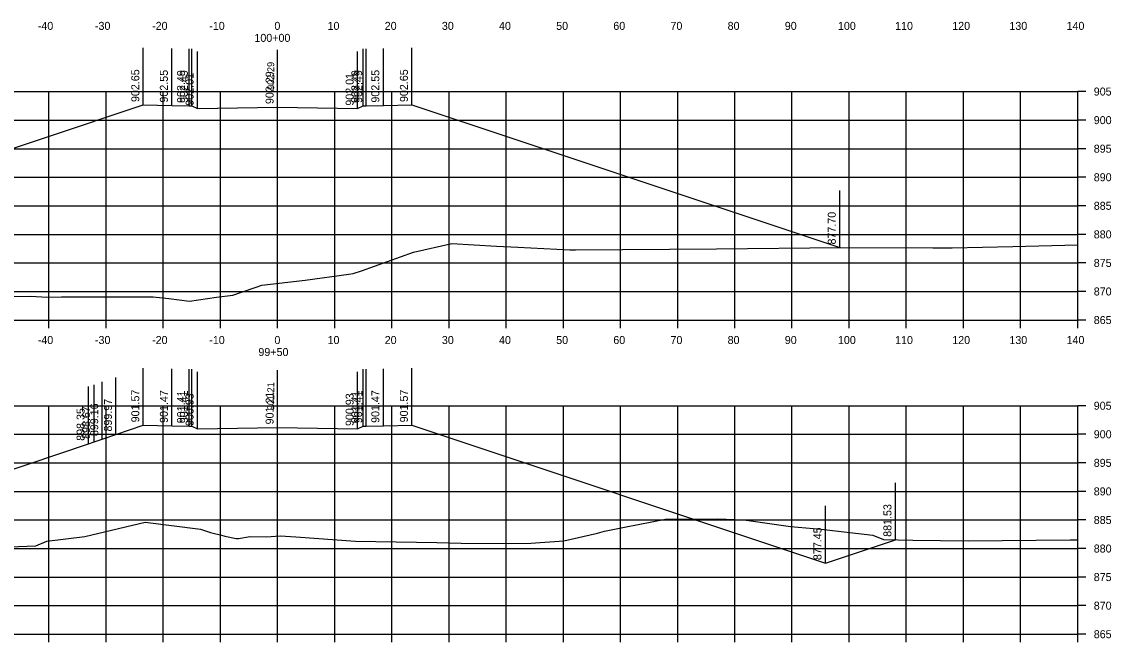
# Model space of a CAD drawing. Extents: x 1098669 to 1198896, y 698679 to 704410.
# Drawn here: x 1111950.8 to 1112141.4, y 701694.6 to 701803.2 of the extents above; entities that cross this region are included whole.
import ezdxf

# ---------------------------------------------------------------- set-up
doc = ezdxf.new("R2010")
doc.units = 0
for name, color, linetype in [('59', 7, 'Continuous'), ('Proposed Surface', 7, 'Continuous'), ('R_Axis', 7, 'Continuous'), ('R_Axis Annot', 7, 'Continuous'), ('R_Fin Surface', 7, 'Continuous'), ('R_Grid', 7, 'Continuous'), ('R_Xsect Elev', 7, 'Continuous')]:
    doc.layers.add(name, color=color, linetype=linetype)

msp = doc.modelspace()

# ---------------------------------------------------------------- linework, layer by layer
at = {"layer": 'Proposed Surface'}
for points in [[(1111945.38, 701755.1), (1111952.3, 701755.23), (1111954.32, 701755.09), (1111955.13, 701755.02), (1111957.71, 701755.07), (1111963.16, 701755.11), (1111971.64, 701755.12), (1111973.75, 701755.12), (1111976.54, 701754.78), (1111980.14, 701754.33), (1111984.83, 701755.05), (1111987.72, 701755.36), (1111989.24, 701755.9), (1111991.82, 701756.8), (1111992.79, 701757.15), (1112000.38, 701757.99), (1112008, 701759.06), (1112008.77, 701759.17), (1112010.21, 701759.64), (1112019.3, 701762.94), (1112026.03, 701764.45), (1112033.84, 701763.99), (1112037.6, 701763.8), (1112046.66, 701763.34), (1112047.11, 701763.32), (1112047.14, 701763.31), (1112047.26, 701763.31), (1112047.66, 701763.31), (1112072.33, 701763.49), (1112094.11, 701763.73), (1112110.22, 701763.69), (1112113.57, 701763.67), (1112124.19, 701763.92), (1112135.55, 701764.22)], [(1111948.71, 701711.3), (1111953.23, 701711.49), (1111955.19, 701712.33), (1111961.8, 701713.15), (1111972.36, 701715.67), (1111982.04, 701714.42), (1111983.8, 701713.85), (1111984.73, 701713.58), (1111985.57, 701713.42), (1111986.32, 701713.18), (1111988.28, 701712.78), (1111988.71, 701712.79), (1111990.74, 701713.13), (1111993.62, 701713.09), (1111995.97, 701713.23), (1111998.76, 701713.09), (1112009.18, 701712.33), (1112023.41, 701712.1), (1112027.65, 701711.95), (1112035.91, 701711.93), (1112039.87, 701711.99), (1112045.66, 701712.35), (1112051.52, 701713.71), (1112052.72, 701714.06), (1112056.27, 701714.77), (1112063.43, 701716.15), (1112066.88, 701716.17), (1112072.51, 701716.24), (1112077.13, 701716.06), (1112085.28, 701714.91), (1112090.68, 701714.44), (1112099.67, 701713.36), (1112101.58, 701712.6), (1112106.69, 701712.49), (1112116.36, 701712.35), (1112134.24, 701712.53), (1112135.55, 701712.57)]]:
    msp.add_lwpolyline(points, dxfattribs=at)
at = {"layer": 'R_Axis'}
for p, q in [((1112135.55, 701751.03), (1112135.55, 701791.03)), ((1112136.95, 701791.03), (1112135.55, 701791.03)), ((1112136.95, 701786.03), (1112135.55, 701786.03)), ((1112136.95, 701781.03), (1112135.55, 701781.03)), ((1112136.95, 701776.03), (1112135.55, 701776.03)), ((1112136.95, 701771.03), (1112135.55, 701771.03)), ((1112136.95, 701766.03), (1112135.55, 701766.03)), ((1112136.95, 701761.03), (1112135.55, 701761.03)), ((1112136.95, 701756.03), (1112135.55, 701756.03)), ((1111855.55, 701751.03), (1112135.55, 701751.03)), ((1111955.55, 701749.63), (1111955.55, 701751.03)), ((1111965.55, 701749.63), (1111965.55, 701751.03)), ((1111975.55, 701749.63), (1111975.55, 701751.03)), ((1111985.55, 701749.63), (1111985.55, 701751.03)), ((1111995.55, 701749.63), (1111995.55, 701751.03)), ((1112005.55, 701749.63), (1112005.55, 701751.03)), ((1112015.55, 701749.63), (1112015.55, 701751.03)), ((1112025.55, 701749.63), (1112025.55, 701751.03)), ((1112035.55, 701749.63), (1112035.55, 701751.03)), ((1112045.55, 701749.63), (1112045.55, 701751.03)), ((1112055.55, 701749.63), (1112055.55, 701751.03)), ((1112065.55, 701749.63), (1112065.55, 701751.03)), ((1112075.55, 701749.63), (1112075.55, 701751.03)), ((1112085.55, 701749.63), (1112085.55, 701751.03)), ((1112095.55, 701749.63), (1112095.55, 701751.03)), ((1112105.55, 701749.63), (1112105.55, 701751.03)), ((1112115.55, 701749.63), (1112115.55, 701751.03)), ((1112125.55, 701749.63), (1112125.55, 701751.03)), ((1112135.55, 701749.63), (1112135.55, 701751.03)), ((1112136.95, 701751.03), (1112135.55, 701751.03)), ((1112135.55, 701696.03), (1112135.55, 701736.03)), ((1112136.95, 701736.03), (1112135.55, 701736.03)), ((1112136.95, 701731.03), (1112135.55, 701731.03)), ((1112136.95, 701726.03), (1112135.55, 701726.03)), ((1112136.95, 701721.03), (1112135.55, 701721.03)), ((1112136.95, 701716.03), (1112135.55, 701716.03)), ((1112136.95, 701711.03), (1112135.55, 701711.03)), ((1112136.95, 701706.03), (1112135.55, 701706.03)), ((1112136.95, 701701.03), (1112135.55, 701701.03)), ((1111855.55, 701696.03), (1112135.55, 701696.03)), ((1111955.55, 701694.63), (1111955.55, 701696.03)), ((1111965.55, 701694.63), (1111965.55, 701696.03)), ((1111975.55, 701694.63), (1111975.55, 701696.03)), ((1111985.55, 701694.63), (1111985.55, 701696.03)), ((1111995.55, 701694.63), (1111995.55, 701696.03)), ((1112005.55, 701694.63), (1112005.55, 701696.03)), ((1112015.55, 701694.63), (1112015.55, 701696.03)), ((1112025.55, 701694.63), (1112025.55, 701696.03)), ((1112035.55, 701694.63), (1112035.55, 701696.03)), ((1112045.55, 701694.63), (1112045.55, 701696.03)), ((1112055.55, 701694.63), (1112055.55, 701696.03)), ((1112065.55, 701694.63), (1112065.55, 701696.03)), ((1112075.55, 701694.63), (1112075.55, 701696.03)), ((1112085.55, 701694.63), (1112085.55, 701696.03)), ((1112095.55, 701694.63), (1112095.55, 701696.03)), ((1112105.55, 701694.63), (1112105.55, 701696.03)), ((1112115.55, 701694.63), (1112115.55, 701696.03)), ((1112125.55, 701694.63), (1112125.55, 701696.03)), ((1112135.55, 701694.63), (1112135.55, 701696.03)), ((1112136.95, 701696.03), (1112135.55, 701696.03))]:
    msp.add_line(p, q, dxfattribs=at)
at = {"layer": 'R_Fin Surface'}
for points in [[(1111900.33, 701764.77), (1111920.41, 701771.45), (1111926.15, 701773.37), (1111937.63, 701777.2), (1111972.05, 701788.68), (1111977.05, 701788.58), (1111980.05, 701788.52), (1111980.55, 701788.52), (1111981.55, 701788.04), (1111995.55, 701788.32), (1112009.55, 701788.04), (1112010.55, 701788.52), (1112011.05, 701788.52), (1112014.05, 701788.58), (1112019.05, 701788.68), (1112093.91, 701763.73)], [(1111946.63, 701724.06), (1111962.48, 701729.37), (1111963.44, 701729.7), (1111964.87, 701730.19), (1111967.27, 701730.99), (1111972.05, 701732.6), (1111977.05, 701732.5), (1111980.05, 701732.44), (1111980.55, 701732.44), (1111981.55, 701731.96), (1111995.55, 701732.24), (1112009.55, 701731.96), (1112010.55, 701732.44), (1112011.05, 701732.44), (1112014.05, 701732.5), (1112019.05, 701732.6), (1112091.41, 701708.48), (1112103.65, 701712.56)]]:
    msp.add_lwpolyline(points, dxfattribs=at)
at = {"layer": 'R_Grid'}
for p, q in [((1111855.55, 701791.03), (1112135.55, 701791.03)), ((1111955.55, 701751.03), (1111955.55, 701791.03)), ((1111965.55, 701751.03), (1111965.55, 701791.03)), ((1111975.55, 701751.03), (1111975.55, 701791.03)), ((1111985.55, 701751.03), (1111985.55, 701791.03)), ((1111995.55, 701751.03), (1111995.55, 701791.03)), ((1112005.55, 701751.03), (1112005.55, 701791.03)), ((1112015.55, 701751.03), (1112015.55, 701791.03)), ((1112025.55, 701751.03), (1112025.55, 701791.03)), ((1112035.55, 701751.03), (1112035.55, 701791.03)), ((1112045.55, 701751.03), (1112045.55, 701791.03)), ((1112055.55, 701751.03), (1112055.55, 701791.03)), ((1112065.55, 701751.03), (1112065.55, 701791.03)), ((1112075.55, 701751.03), (1112075.55, 701791.03)), ((1112085.55, 701751.03), (1112085.55, 701791.03)), ((1112095.55, 701751.03), (1112095.55, 701791.03)), ((1112105.55, 701751.03), (1112105.55, 701791.03)), ((1112115.55, 701751.03), (1112115.55, 701791.03)), ((1112125.55, 701751.03), (1112125.55, 701791.03)), ((1112135.55, 701751.03), (1112135.55, 701791.03)), ((1111855.55, 701786.03), (1112135.55, 701786.03)), ((1111855.55, 701781.03), (1112135.55, 701781.03)), ((1111855.55, 701776.03), (1112135.55, 701776.03)), ((1111855.55, 701771.03), (1112135.55, 701771.03)), ((1111855.55, 701766.03), (1112135.55, 701766.03)), ((1111855.55, 701761.03), (1112135.55, 701761.03)), ((1111855.55, 701756.03), (1112135.55, 701756.03)), ((1111855.55, 701751.03), (1112135.55, 701751.03)), ((1111855.55, 701736.03), (1112135.55, 701736.03)), ((1111955.55, 701696.03), (1111955.55, 701736.03)), ((1111965.55, 701696.03), (1111965.55, 701736.03)), ((1111975.55, 701696.03), (1111975.55, 701736.03)), ((1111985.55, 701696.03), (1111985.55, 701736.03)), ((1111995.55, 701696.03), (1111995.55, 701736.03)), ((1112005.55, 701696.03), (1112005.55, 701736.03)), ((1112015.55, 701696.03), (1112015.55, 701736.03)), ((1112025.55, 701696.03), (1112025.55, 701736.03)), ((1112035.55, 701696.03), (1112035.55, 701736.03)), ((1112045.55, 701696.03), (1112045.55, 701736.03)), ((1112055.55, 701696.03), (1112055.55, 701736.03)), ((1112065.55, 701696.03), (1112065.55, 701736.03)), ((1112075.55, 701696.03), (1112075.55, 701736.03)), ((1112085.55, 701696.03), (1112085.55, 701736.03)), ((1112095.55, 701696.03), (1112095.55, 701736.03)), ((1112105.55, 701696.03), (1112105.55, 701736.03)), ((1112115.55, 701696.03), (1112115.55, 701736.03)), ((1112125.55, 701696.03), (1112125.55, 701736.03)), ((1112135.55, 701696.03), (1112135.55, 701736.03)), ((1111855.55, 701731.03), (1112135.55, 701731.03)), ((1111855.55, 701726.03), (1112135.55, 701726.03)), ((1111855.55, 701721.03), (1112135.55, 701721.03)), ((1111855.55, 701716.03), (1112135.55, 701716.03)), ((1111855.55, 701711.03), (1112135.55, 701711.03)), ((1111855.55, 701706.03), (1112135.55, 701706.03)), ((1111855.55, 701701.03), (1112135.55, 701701.03)), ((1111855.55, 701696.03), (1112135.55, 701696.03))]:
    msp.add_line(p, q, dxfattribs=at)
at = {"layer": 'R_Xsect Elev'}
for p, q in [((1111972.05, 701788.68), (1111972.05, 701798.68)), ((1111977.05, 701788.58), (1111977.05, 701798.58)), ((1111980.05, 701788.52), (1111980.05, 701798.52)), ((1111980.55, 701788.52), (1111980.55, 701798.52)), ((1111981.55, 701788.04), (1111981.55, 701798.04)), ((1111995.55, 701788.32), (1111995.55, 701798.32)), ((1111995.55, 701788.32), (1111995.55, 701798.32)), ((1112009.55, 701788.04), (1112009.55, 701798.04)), ((1112010.55, 701788.52), (1112010.55, 701798.52)), ((1112011.05, 701788.52), (1112011.05, 701798.52)), ((1112014.05, 701788.58), (1112014.05, 701798.58)), ((1112019.05, 701788.68), (1112019.05, 701798.68)), ((1112093.91, 701763.73), (1112093.91, 701773.73)), ((1111972.05, 701732.6), (1111972.05, 701742.6)), ((1111977.05, 701732.5), (1111977.05, 701742.5)), ((1111980.05, 701732.44), (1111980.05, 701742.44)), ((1111980.55, 701732.44), (1111980.55, 701742.44)), ((1111981.55, 701731.96), (1111981.55, 701741.96)), ((1111995.55, 701732.24), (1111995.55, 701742.24)), ((1111995.55, 701732.24), (1111995.55, 701742.24)), ((1112009.55, 701731.96), (1112009.55, 701741.96)), ((1112010.55, 701732.44), (1112010.55, 701742.44)), ((1112011.05, 701732.44), (1112011.05, 701742.44)), ((1112014.05, 701732.5), (1112014.05, 701742.5)), ((1112019.05, 701732.6), (1112019.05, 701742.6)), ((1111964.87, 701730.19), (1111964.87, 701740.19)), ((1111967.27, 701730.99), (1111967.27, 701740.99)), ((1111962.48, 701729.37), (1111962.48, 701739.37)), ((1111963.44, 701729.7), (1111963.44, 701739.7)), ((1112103.65, 701712.56), (1112103.65, 701722.56)), ((1112091.41, 701708.48), (1112091.41, 701718.48))]:
    msp.add_line(p, q, dxfattribs=at)

# ---------------------------------------------------------------- texts
at = {"layer": '59'}
for s, p in [(' 902.65', (1111971.35, 701788.68)), (' 902.55', (1111976.35, 701788.58)), (' 902.49', (1111979.35, 701788.52)), (' 902.49', (1111979.85, 701788.52)), (' 902.01', (1111980.85, 701788.04)), (' 902.29', (1111994.85, 701788.32)), (' 902.01', (1112008.85, 701788.04)), (' 902.49', (1112009.85, 701788.52)), (' 902.49', (1112010.35, 701788.52)), (' 902.55', (1112013.35, 701788.58)), (' 902.65', (1112018.35, 701788.68)), (' 877.70', (1112093.21, 701763.73)), (' 901.57', (1111971.35, 701732.6)), (' 901.47', (1111976.35, 701732.5)), (' 901.41', (1111979.35, 701732.44)), (' 901.41', (1111979.85, 701732.44)), (' 900.93', (1111980.85, 701731.96)), (' 901.21', (1111994.85, 701732.24)), (' 900.93', (1112008.85, 701731.96)), (' 901.41', (1112009.85, 701732.44)), (' 901.41', (1112010.35, 701732.44)), (' 901.47', (1112013.35, 701732.5)), (' 901.57', (1112018.35, 701732.6)), (' 899.16', (1111964.17, 701730.19)), (' 899.97', (1111966.57, 701730.99)), (' 898.35', (1111961.78, 701729.37)), (' 898.67', (1111962.74, 701729.7)), (' 881.53', (1112102.95, 701712.56)), (' 877.45', (1112090.71, 701708.48))]:
    msp.add_text(s, height=1.4, rotation=90, dxfattribs=at).set_placement(p)
at = {"layer": 'R_Axis Annot'}
for s, p in [('-40', (1111953.59, 701801.83)), ('-30', (1111963.59, 701801.83)), ('-20', (1111973.59, 701801.83)), ('-10', (1111983.59, 701801.83)), ('0', (1111994.99, 701801.83)), ('10', (1112004.29, 701801.83)), ('20', (1112014.29, 701801.83)), ('30', (1112024.29, 701801.83)), ('40', (1112034.29, 701801.83)), ('50', (1112044.29, 701801.83)), ('60', (1112054.29, 701801.83)), ('70', (1112064.29, 701801.83)), ('80', (1112074.29, 701801.83)), ('90', (1112084.29, 701801.83)), ('100', (1112093.59, 701801.83)), ('110', (1112103.59, 701801.83)), ('120', (1112113.59, 701801.83)), ('130', (1112123.59, 701801.83)), ('140', (1112133.59, 701801.83)), ('100+00', (1111991.49, 701799.73)), ('905', (1112138.35, 701790.33)), ('900', (1112138.35, 701785.33)), ('895', (1112138.35, 701780.33)), ('890', (1112138.35, 701775.33)), ('885', (1112138.35, 701770.33)), ('880', (1112138.35, 701765.33)), ('875', (1112138.35, 701760.33)), ('870', (1112138.35, 701755.33)), ('865', (1112138.35, 701750.33)), ('-40', (1111953.59, 701746.83)), ('-30', (1111963.59, 701746.83)), ('-20', (1111973.59, 701746.83)), ('-10', (1111983.59, 701746.83)), ('0', (1111994.99, 701746.83)), ('10', (1112004.29, 701746.83)), ('20', (1112014.29, 701746.83)), ('30', (1112024.29, 701746.83)), ('40', (1112034.29, 701746.83)), ('50', (1112044.29, 701746.83)), ('60', (1112054.29, 701746.83)), ('70', (1112064.29, 701746.83)), ('80', (1112074.29, 701746.83)), ('90', (1112084.29, 701746.83)), ('100', (1112093.59, 701746.83)), ('110', (1112103.59, 701746.83)), ('120', (1112113.59, 701746.83)), ('130', (1112123.59, 701746.83)), ('140', (1112133.59, 701746.83)), ('99+50', (1111992.19, 701744.73)), ('905', (1112138.35, 701735.33)), ('900', (1112138.35, 701730.33)), ('895', (1112138.35, 701725.33)), ('890', (1112138.35, 701720.33)), ('885', (1112138.35, 701715.33)), ('880', (1112138.35, 701710.33)), ('875', (1112138.35, 701705.33)), ('870', (1112138.35, 701700.33)), ('865', (1112138.35, 701695.33))]:
    msp.add_text(s, height=1.4, dxfattribs=at).set_placement(p)
at = {"layer": 'R_Xsect Elev'}
for s, p in [('902.29', (1111994.95, 701791.32)), ('901.21', (1111994.95, 701735.24))]:
    msp.add_text(s, height=1.2, rotation=90, dxfattribs=at).set_placement(p)

doc.saveas('drawing.dxf')
